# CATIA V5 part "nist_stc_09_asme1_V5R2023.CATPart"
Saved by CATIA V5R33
Part number: NIST PMI FTC 09 ASME1
Revision: D
Description: NIST PMI test model downloaded from http://go.usa.gov/mGVm
Bounding box of the stored display mesh (mm): x -95.25 to 95.25, y 0 to 9.642, z -139.7 to 139.7
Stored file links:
  C:\Users\rla3\OneDrive - NIST\STEP\NIST Test Models\STC\NIST_STC\09\V5\nist_stc_09_asme1_V5R2023-20231206.CATPart
  E:\users\dgn\TPS V5\Import-export annotations\Step\PMI representation 2015\NIST UC\nist_ftc_09_asme1_ct5240_rd - 0.CATPart
  E:\DownloadOfCXR29\win_b64\resources\graphic\CATTPSGeneralTolerance.xlsx
  C:\Program Files\Dassault Systemes\B32\win_b64\resources\graphic\CATTPSGeneralTolerance.xlsx
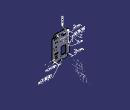
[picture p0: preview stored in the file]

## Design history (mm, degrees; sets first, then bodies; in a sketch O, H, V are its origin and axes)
TTRSSet1
f4a2d38f3ddc11d3a929006094b99c4b_11 "CATTPSSet"
Set1 "MBD_A_PMI"
  Plane1: type Equation, A -0.57735, B 0.57735, C 0.57735, Length 20, RefPoint vertex [face of Chamfer4 | end face of Pad1 | face of Pad1 from Sketch7.L15]
  Point1: type Center, Curve edge [end face of Pad1 | face of Chamfer1]
  Plane2: type OffsetPt, RefPlane face of Pad1 from Sketch7.L15, RefPoint Point1
  Intersect1: ToIntersect1 Chamfer1, ToIntersect2 Plane2
Set2 "MBD_B"
  Sketch1 on end face of Pad1, origin (0, 3.0378, 0), H (-1, 0, 0), V (0, 0, 1)
    arc A1 centre (-50.8, 12.7) radius 34.29 from (-66.509, -17.78) to (-81.28, -3.009) ccw
    point P1 (-50.8, 12.7)
    point P2 (-81.28, -3.009)
    point P3 (-66.509, -17.78)
    line L1 (-64.0699, -20.2137) -> (-63.1677, -17.9758)
    point P5 (-63.1677, -17.9758)
    line L2 (-81.28, -3.009) -> (-83.717, -0.5681)
    line L3 (-83.717, -0.5681) -> (-81.4789, 0.334)
    line L4 (-81.4789, 0.334) -> (-81.28, -3.009)
    polyline C1
    construction line L5 (-50.8, 12.7) -> (-53.3201, 12.7)
    construction line L6 (-50.8, 12.7) -> (-50.8, 10.3697)
    reference projected arc E1 centre (-50.8, 12.7) radius 4.7625 from (-52.578, 17.1182) to (-49.022, 17.1182) ccw from edge [end face of Pad1 | face of Pocket2 from Sketch15.A1]
    point P10 (-63.6219, -19.1025)
    line L7 (-66.509, -17.78) -> (-63.1677, -17.9758)
    line L8 (-66.5086, -17.7802) -> (-64.0704, -20.2149)
    point P12 (-66.5086, -17.7802)
    point P13 (-64.0704, -20.2149)
    radius A1 = 34.29
    distance L5 P3 = 30.48
    distance L6 P2 = 30.48
    length L1 = 2.413
    distance L1 P3 = 3.1722
    angle L1 L7 = 71.3955
    length L8 = 3.4456
    angle L8 L1 = 67
    length L3 = 2.413
    distance L3 P2 = 3.175
    angle L3 L2 = 67
    coincidence: L1 P1, L3 P1, P10 L1, P10 A1, L7 P5, P12 A1, P13 L1
    horizontal: L5 H
    vertical: L6 V
    concentricity: E1 P1
  Sketch2 on end face of Pad1, origin (0, 3.0378, 0), H (-1, 0, 0), V (0, 0, 1)
    reference projected circle E1 centre (57.15, 38.4) radius 3.175 from edge [end face of Pad1 | face of RectPattern2]
    reference projected circle E2 centre (0.15, -101.6) radius 3.175 from edge [end face of Pad1 | face of RectPattern2]
    axis line L1 (0.15, -101.6) -> (57.15, 38.4)
    point P1 (0.15, -101.6)
    point P2 (57.15, 38.4)
    point P3 (28.65, -31.6)
    concentricity: P1 E2, P2 E1
    midpoint: P3 L1
    coincidence: P3 L1
  AxisSystem1 "AF": origin (-28.65, 3.0378, -31.6), X (1, 0, 0), Y (0, 1, 0), Z (0, 0, 1)
  AxisSystem2 "ABC": origin (-82.55, 3.0378, 107.95), X (1, 0, 0), Y (0, 0, -1), Z (0, 1, 0)
Set3 "MBD_C"
  Sketch3 on end face of Pad1, origin (0, 3.0378, 0), H (-1, 0, 0), V (0, 0, 1)
    reference projected circle E1 centre (-50.8, -15.24) radius 1.9844 from edge [end face of Pad1 | face of Hole7]
    point P1 (-50.8, -15.24)
    line L1 (-50.8, -10.16) -> (-50.8, -20.32)
    point P2 (-50.8, -10.16)
    reference projected circle E2 centre (-78.74, 12.7) radius 1.9844 from edge [end face of Pad1 | face of CircPattern1]
    point P4 (-78.74, 12.7)
    line L2 (-83.82, 12.7) -> (-73.66, 12.7)
    point P5 (-83.82, 12.7)
    reference projected circle E3 centre (-70.5566, -7.0566) radius 1.9844 from edge [end face of Pad1 | face of CircPattern1]
    line L3 (-66.9645, -3.4645) -> (-74.1487, -10.6487)
    point P7 (-66.9645, -3.4645)
    point P8 (-74.1487, -10.6487)
    point P9 (-70.5566, -7.0566)
    point P10 (-50.8, 12.7)
    point P11 (-66.6352, -10.3194)
    arc A1 centre (-50.8, 12.7) radius 27.94 from (-73.8194, -3.1352) to (-66.6352, -10.3194) ccw
    point P12 (-73.8194, -3.1352)
    construction line L4 (-50.8, 12.7) -> (-89.9713, -15.3816)
    angle L1 L3 = 45
    radius A1 = 27.94
    length L2 = 10.16
    distance P4 P5 = 5.08
    length L3 = 10.16
    distance P9 P8 = 5.08
    length L1 = 10.16
    distance P1 P2 = 5.08
    distance L3 P12 = 5.08
    distance L3 P11 = 5.08
    concentricity: P1 E1, P4 E2, P9 E3
    vertical: L1 V
    coincidence: L1 P1, L2 P4, P9 L3, P10 L3, P10 L2
    horizontal: L2 H
  AxisSystem3 "AGH": origin (50.8, 3.0378, 12.7), X (1, 0, 0), Y (0, 0, -1), Z (0, 1, 0)
  Sketch4 on end face of Pad1, origin (0, 3.0378, 0), H (-1, 0, 0), V (0, 0, 1)
    arc A1 centre (-50.8, 12.7) radius 25.9556 from (-69.1534, -5.6534) to (-72.7556, -1.1436) cw
    point P2 (-69.1534, -5.6534)
    reference projected circle E1 centre (-70.5566, -7.0566) radius 1.9844 from edge [end face of Pad1 | face of CircPattern1]
    reference projected arc E2 centre (-50.8, 12.7) radius 27.94 from (-73.8194, -3.1352) to (-66.6352, -10.3194) ccw from Sketch3.A1
    reference projected line E3 (-66.9645, -3.4645) -> (-74.1487, -10.6487) from Sketch3.L3
    arc A2 centre (-50.8, 12.7) radius 29.9244 from (-71.9597, -8.4597) to (-76.2178, -3.0926) cw
    point P5 (-71.9597, -8.4597)
    reference projected circle E4 centre (-70.5566, -7.0566) radius 1.9844 from edge [end face of Pad1 | face of CircPattern1]
    reference projected arc E5 centre (-50.8, 12.7) radius 27.94 from (-73.8194, -3.1352) to (-66.6352, -10.3194) ccw from Sketch3.A1
    reference projected line E6 (-66.9645, -3.4645) -> (-74.1487, -10.6487) from Sketch3.L3
    tangency: A1 E1, A2 E4
    concentricity: A1 E2, A2 E5
    coincidence: P2 E3, P5 E6
  Sketch5 on end face of Pad1, origin (0, 3.0378, 0), H (-1, 0, 0), V (0, 0, 1)
    line L1 (-50.8, 12.7) -> (-77.7835, -8.4552)
    point P1 (-50.8, 12.7)
    point P3 (-74.3496, -5.763)
    reference projected arc E1 centre (-50.8, 12.7) radius 29.9244 from (-76.2178, -3.0926) to (-71.9597, -8.4597) ccw from Sketch4.A2
    reference projected point E2 (-50.8, 12.7) from vertex [YZ plane of AxisSystem3 | ZX plane of AxisSystem3 | XY plane of AxisSystem3]
    point P4 (-71.2263, -3.3144)
    reference projected arc E3 centre (-50.8, 12.7) radius 25.9556 from (-72.7556, -1.1436) to (-69.1534, -5.6534) ccw from Sketch4.A1
    coincidence: P3 L1, P3 E1, P1 E2, P4 L1, P4 E3
  Line1: type PtPt, FirstPoint Sketch3.P8, SecondPoint Sketch3.P7
  Extrude1: Element1 Line1, Lim1 2.54, Lim2 0, Direction end face of Pad1
Set4 "MBD_D"
  Sketch6 on end face of Pad1, origin (0, 3.0378, 0), H (-1, 0, 0), V (0, 0, 1)
    reference projected circle E1 centre (-66.0374, 91.44) radius 3.5687 from edge [end face of Pad1 | face of RectPattern5]
    point P1 (-66.0374, 91.44)
    line L1 (-71.1174, 91.44) -> (-60.9574, 91.44)
    point P2 (-71.1174, 91.44)
    line L2 (-66.0374, 96.52) -> (-66.0374, 86.36)
    point P4 (-66.0374, 96.52)
    length L2 = 10.16
    distance P4 L1 = 5.08
    length L1 = 10.16
    distance P2 L2 = 5.08
    concentricity: P1 E1
    horizontal: L1 H
    coincidence: P1 L1, P1 L2
    vertical: L2 V
  AxisSystem4 "ADB": origin (-31.75, 3.0378, 91.44), X (1, 0, 0), Y (0, 0, -1), Z (0, 1, 0)
  AxisSystem5 "ABC": origin (-82.55, 3.0378, 107.95), X (1, 0, 0), Y (0, 0, -1), Z (0, 1, 0)
Set5 "MBD_A"
  AxisSystem6 "ABC": origin (-82.55, 3.0378, 107.95), X (1, 0, 0), Y (0, 0, -1), Z (0, 1, 0)
Set6
  Point2: type Center, Curve edge [end face of Pad1 | face of Chamfer1]
  Point3: type Center, Curve edge [end face of Pad1 | face of Pocket2 from Sketch15.A1]
  Point4: type Center, Curve edge [end face of Pad1 | face of Hole5]
  Plane3: type Between, Element1 face of Pocket3 from Sketch17.L3, Element2 face of Pocket3 from Sketch17.L2, Ratio 0.5
  Extract1: ExtractElem face of Pocket3 from Sketch17.A2
  Extract2: ExtractElem face of Pocket3 from Sketch17.A1
  Intersect2: ToIntersect1 Plane3, ToIntersect2 Extract1
  Intersect3: ToIntersect1 Plane3, ToIntersect2 Extract2
  Point5: type OnCurve, Support Intersect2, Ratio 0.5
  Point6: type OnCurve, Support Intersect3, Ratio 0.5
  Plane4: type Tangent, Support Extract1, RefPoint Point5
  Plane5: type Tangent, Support Extract2, RefPoint Point6
  Plane6: type Between, Element1 face of RectPattern6, Element2 face of RectPattern6, Ratio 0.5
  Extract3: ExtractElem face of RectPattern6
  Extract4: ExtractElem face of RectPattern6
  Intersect4: ToIntersect1 Plane6, ToIntersect2 Extract4
  Intersect5: ToIntersect1 Plane6, ToIntersect2 Extract3
  Point7: type OnCurve, Support Intersect4, Ratio 0.5
  Point8: type OnCurve, Support Intersect5, Ratio 0.5
  Plane7: type Tangent, Support Extract4, RefPoint Point7
  Plane8: type Tangent, Support Extract3, RefPoint Point8
Body1 (main body)
  Sketch7 on zx-plane, origin (0, 0, 0), H (-1, 0, 0), V (0, 0, 1)
    line L1 (-74.6125, 139.7) -> (74.6125, 139.7)
    line L2 (95.25, 117.475) -> (95.25, -117.475)
    construction line L3 (74.6125, -139.7) -> (-74.6125, -139.7)
    line L4 (-95.25, -117.475) -> (-95.25, 117.475)
    construction line L5 (0, -160) -> (0, 150)
    axis line L6 (150, 0) -> (-110, 0)
    line L7 (-74.6125, 139.7) -> (-74.6125, 117.475)
    line L8 (-74.6125, 117.475) -> (-95.25, 117.475)
    line L9 (74.6125, 139.7) -> (74.6125, 117.475)
    line L10 (74.6125, 117.475) -> (95.25, 117.475)
    line L11 (-95.25, -117.475) -> (-74.6125, -117.475)
    line L12 (-74.6125, -117.475) -> (-74.6125, -139.7)
    line L13 (95.25, -117.475) -> (74.6125, -117.475)
    line L14 (74.6125, -117.475) -> (74.6125, -139.7)
    line L15 (-74.6125, -139.7) -> (74.6125, -139.7)
    distance L1 L3 = 279.4
    distance L4 L2 = 190.5
    distance L5 L4 = 95.25
    distance L3 L6 = 139.7
    length L4 = 234.95
    length L3 = 149.225
    distance L12 L5 = 74.6125
    distance L6 L11 = 117.475
    horizontal: L6 H, L3 H, L1 H, L8 H, L10 H, L11 H, L13 H
    coincidence: L5 V, L6 H, L10 L8, L14 L9, L11 L13, L12 L7
    vertical: L2 V, L4 V, L14 V, L9 V, L12 V, L7 V
  Pad1: profile Sketch7, direction (0, 1, 0), length 3.0378
  Sketch8 on end face of Pad1, origin (75.874, 3.0378, 103.1133), H (1, 0, 0), V (0, 0, -1)
    point P1 (6.676, -4.8367)
    reference intersected line E1 through (-75.874, 0) direction (0, 1) from yz-plane
    reference intersected line E2 through (0, 103.1133) direction (1, 0) from xy-plane
    distance P1 E1 = 82.55
    distance E2 P1 = 107.95
  Hole1: placed by Sketch8, at (82.55, 3.0378, 107.95) direction (0, -1, 0), diameter 5.9436, through (limit type 6)
  Fillet1: radius 6.35, on edge [face of Pad1 from Sketch7.L8 | face of Pad1 from Sketch7.L7]; edge [face of Pad1 from Sketch7.L9 | face of Pad1 from Sketch7.L10]; edge [face of Pad1 from Sketch7.L13 | face of Pad1 from Sketch7.L14]; edge [face of Pad1 from Sketch7.L12 | face of Pad1 from Sketch7.L11]
  Sketch9 on end face of Pad1, origin (32.8752, 3.0378, 131.8981), H (1, 0, 0), V (0, 0, -1)
    point P1 (-13.8252, 261.4381)
    reference intersected line E2 through (-32.8752, 0) direction (0, 1) from yz-plane
    reference intersected line E3 through (0, 131.8981) direction (1, 0) from xy-plane
    distance P1 E2 = 19.05
    distance E3 P1 = 129.54
  Hole2: placed by Sketch9, at (19.05, 3.0378, -129.54) direction (0, -1, 0), diameter 6.35, through (limit type 6)
  RectPattern1: of Hole2, direction 1 instances 3, spacing 19.05, along edge [face of Pad1 from Sketch7.L1 | end face of Pad1] reversed
  Sketch10 on end face of Pad1, origin (53.7045, 3.0378, 105.0288), H (1, 0, 0), V (0, 0, -1)
    point P1 (-110.8545, 206.6288)
    reference intersected line E1 through (-53.7045, 0) direction (0, 1) from yz-plane
    reference intersected line E2 through (0, 105.0288) direction (1, 0) from xy-plane
    distance P1 E1 = 57.15
    distance E2 P1 = 101.6
  Hole3: placed by Sketch10, at (-57.15, 3.0378, -101.6) direction (0, -1, 0), diameter 6.35, through (limit type 6)
  RectPattern2: of Hole3, direction 1 instances 2, spacing 57, along edge [face of Pad1 from Sketch7.L1 | end face of Pad1], direction 2 instances 2, spacing 140, along edge [face of Pad1 from Sketch7.L4 | end face of Pad1] reversed
  Sketch11 on end face of Pad1, origin (0, 3.0378, 0), H (-1, 0, 0), V (0, 0, 1)
    point P1 (5.649, -11.6078)
    line L1 (5.649, -11.6078) -> (24.3053, -11.6078)
    line L2 (55.649, -11.6078) -> (55.649, -45.2528)
    line L3 (55.649, -91.6078) -> (37.0053, -91.6078)
    line L4 (5.649, -91.6078) -> (5.649, -57.9528)
    point P2 (55.649, -11.6078)
    point P4 (5.649, -91.6078)
    arc A1 centre (55.649, -51.6028) radius 6.35 from (55.649, -57.9528) to (55.649, -45.2528) ccw
    point P5 (55.649, -51.6028)
    arc A2 centre (30.6553, -11.6078) radius 6.35 from (37.0053, -11.6078) to (24.3053, -11.6078) ccw
    point P6 (30.6553, -11.6078)
    arc A3 centre (5.649, -51.6028) radius 6.35 from (5.649, -45.2528) to (5.649, -57.9528) ccw
    point P7 (5.649, -51.6028)
    arc A4 centre (30.6553, -91.6078) radius 6.35 from (24.3053, -91.6078) to (37.0053, -91.6078) ccw
    point P8 (30.6553, -91.6078)
    construction line L5 (30.6553, 11.6851) -> (30.6553, -11.6078)
    axis line L6 (55.649, -51.6028) -> (5.649, -51.6028)
    line L7 (55.649, -57.9528) -> (55.649, -91.6078)
    line L8 (5.649, -45.2528) -> (5.649, -11.6078)
    line L9 (37.0053, -11.6078) -> (55.649, -11.6078)
    line L10 (24.3053, -91.6078) -> (5.649, -91.6078)
    reference intersected line E1 through (0, 0) direction (-1, 0) from xy-plane
    reference intersected line E2 through (0, 0) direction (0, -1) from yz-plane
    distance L6 L3 = 40.005
    distance L5 L4 = 25.0063
    radius A2 = 6.35
    radius A1 = 6.35
    radius A4 = 6.35
    radius A3 = 6.35
    distance P4 P1 = 80
    distance P1 P2 = 50
    distance L9 E1 = 11.6078
    distance L8 E2 = 5.649
    horizontal: L1 H, L3 H
    vertical: L2 V, L4 V
    coincidence: P7 L4, P6 L1, P8 L3, P5 L2, P8 L5, L2 L7, L9 L1, L3 L10, L8 L4
  Pocket1: profile Sketch11, direction (0, -1, 0), through (limit type 6)
  RectPattern3: of Hole1, direction 1 instances 2, spacing 165.1, along edge [face of Pad1 from Sketch7.L1 | end face of Pad1] reversed, direction 2 instances 2, spacing 215.9, along edge [face of Pad1 from Sketch7.L4 | end face of Pad1]
  Chamfer1: length 0.762, second length 0.762, on edge [end face of Pad1 | face of Hole1]; edge [end face of Pad1 | face of RectPattern3] (x3)
  Chamfer2: length 6.35, second length 6.35, on edge [face of Pad1 from Sketch7.L4 | face of Pad1 from Sketch7.L8]; edge [face of Pad1 from Sketch7.L10 | face of Pad1 from Sketch7.L2]; edge [face of Pad1 from Sketch7.L11 | face of Pad1 from Sketch7.L4]; edge [face of Pad1 from Sketch7.L2 | face of Pad1 from Sketch7.L13]
  Chamfer3: length 12.7, angle 30, on edge [face of Pad1 from Sketch7.L7 | face of Pad1 from Sketch7.L1]; edge [face of Pad1 from Sketch7.L1 | face of Pad1 from Sketch7.L9]
  Chamfer4: length 12.7, angle 30, on edge [face of Pad1 from Sketch7.L15 | face of Pad1 from Sketch7.L12]; edge [face of Pad1 from Sketch7.L14 | face of Pad1 from Sketch7.L15]
  Sketch12 on end face of Pad1, origin (53.7613, 3.0378, -81.0134), H (1, 0, 0), V (0, 0, -1)
    point P1 (-104.5613, -172.4534)
    reference intersected line E1 through (0, -81.0134) direction (1, 0) from xy-plane
    reference intersected line E2 through (-53.7613, 0) direction (0, 1) from yz-plane
    distance P1 E1 = 91.44
    distance E2 P1 = 50.8
  Hole4: placed by Sketch12, at (-50.8, 3.0378, 91.44) direction (0, -1, 0), diameter 5.6134, through (limit type 6)
  RectPattern4: of Hole4, direction 1 instances 2, spacing 38.1, along edge [face of Pad1 from Sketch7.L15 | end face of Pad1] reversed, direction 2 instances 2, spacing 215.9
  Sketch13 on end face of Pad1, origin (33.0099, 3.0378, -92.3254), H (1, 0, 0), V (0, 0, -1)
    point P1 (-64.7599, -183.7654)
    reference intersected line E1 through (0, -92.3254) direction (1, 0) from xy-plane
    reference intersected line E2 through (-33.0099, 0) direction (0, 1) from yz-plane
    distance P1 E1 = 91.44
    distance E2 P1 = 31.75
  Hole5: placed by Sketch13, at (-31.75, 3.0378, 91.44) direction (0, -1, 0), diameter 19.05, through (limit type 6)
  Sketch14 on end face of Pad1, origin (-47.4372, 3.0378, -73.8358), H (1, 0, 0), V (0, 0, -1)
    point P1 (75.3745, -165.2758)
    reference intersected line E1 through (0, -73.8358) direction (1, 0) from xy-plane
    reference intersected line E2 through (47.4372, 0) direction (0, 1) from yz-plane
    distance E1 P1 = 91.44
    distance E2 P1 = 27.9374
  Hole6: placed by Sketch14, at (27.9374, 3.0378, 91.44) direction (0, -1, 0), diameter 7.1374, through (limit type 6)
  RectPattern5: of Hole6, direction 1 instances 3, spacing 19.05, along edge [face of Pad1 from Sketch7.L15 | end face of Pad1] reversed, direction 2 instances 2, spacing 215.9
  Sketch15 on end face of Pad1, origin (0, 3.0378, 0), H (-1, 0, 0), V (0, 0, 1)
    arc A1 centre (-50.8, 12.7) radius 4.7625 from (-52.578, 17.1182) to (-49.022, 17.1182) ccw
    point P1 (-50.8, 12.7)
    axis line L1 (-50.8, 12.7) -> (-50.8, 29.6508)
    line L2 (-52.578, 20.32) -> (-52.578, 17.1182)
    line L3 (-49.022, 20.32) -> (-49.022, 17.1182)
    arc A2 centre (-50.8, 20.32) radius 1.778 from (-49.022, 20.32) to (-52.578, 20.32) ccw
    point P3 (-50.8, 20.32)
    point P4 (-49.022, 20.32)
    reference intersected line E1 through (0, 0) direction (-1, 0) from xy-plane
    reference intersected line E2 through (0, 0) direction (0, -1) from yz-plane
    radius A1 = 4.7625
    distance L3 L2 = 3.556
    distance P1 P3 = 7.62
    distance E1 P1 = 12.7
    distance E2 L1 = 50.8
    vertical: L1 V, L2 V, L3 V
    coincidence: P3 L1, A2 P4, P4 L3
    tangency: A2 L3, A2 L2
  Pocket2: profile Sketch15, direction (0, -1, 0), through (limit type 6)
  Sketch16 on end face of Pad1, origin (-52.5866, 3.0378, 15.7994), H (1, 0, 0), V (0, 0, -1)
    point P1 (103.3866, 31.0394)
    reference intersected line E1 through (0, 15.7994) direction (1, 0) from xy-plane
    reference intersected line E2 through (52.5866, 0) direction (0, 1) from yz-plane
    distance P1 E1 = 15.24
    distance E2 P1 = 50.8
  Hole7: placed by Sketch16, at (50.8, 3.0378, -15.24) direction (0, -1, 0), diameter 3.9688, through (limit type 6)
  CircPattern1: of Hole7, instances 3, angular step 45, axis from face of Pocket2 from Sketch15.A1
  Sketch17 on end face of Pad1, origin (0, 3.0378, 0), H (-1, 0, 0), V (0, 0, 1)
    construction line L1 (-57.15, -95.25) -> (-38.1, -95.25)
    line L2 (-57.15, -92.075) -> (-38.1, -92.075)
    line L3 (-38.1, -98.425) -> (-57.15, -98.425)
    arc A1 centre (-38.1, -95.25) radius 3.175 from (-38.1, -92.075) to (-38.1, -98.425) cw
    arc A2 centre (-57.15, -95.25) radius 3.175 from (-57.15, -98.425) to (-57.15, -92.075) cw
    axis line L4 (-47.625, -92.075) -> (-47.625, -98.425)
    point P7 (-47.625, -92.075)
    point P8 (-47.625, -98.425)
    reference intersected line E1 through (0, 0) direction (-1, 0) from xy-plane
    reference intersected line E2 through (0, 0) direction (0, -1) from yz-plane
    distance L1 L2 = 3.175
    distance A2 A1 = 25.4
    distance E1 L1 = 95.25
    distance L4 E2 = 47.625
    horizontal: L1 H
    tangency: A1 L2, A2 L2, A1 L3, A2 L3
    vertical: L4 V
    midpoint: P7 L2, L3 P8
  Pocket3: profile Sketch17, direction (0, -1, 0), through (limit type 6)
  RectPattern6: of Pocket3, direction 1 instances 2, spacing 19.05, along edge [face of Pad1 from Sketch7.L2 | end face of Pad1], direction 2 instances 2, spacing 215.9
  Sketch18 on end face of Pad1, origin (0, 3.0378, 0), H (-1, 0, 0), V (0, 0, 1)
    construction line L1 (-61.9125, -50.8) -> (-33.3375, -50.8)
    line L2 (-61.9125, -46.0375) -> (-33.3375, -46.0375)
    line L3 (-33.3375, -55.5625) -> (-61.9125, -55.5625)
    arc A1 centre (-33.3375, -50.8) radius 4.7625 from (-33.3375, -46.0375) to (-33.3375, -55.5625) cw
    arc A2 centre (-61.9125, -50.8) radius 4.7625 from (-61.9125, -55.5625) to (-61.9125, -46.0375) cw
    axis line L4 (-47.625, -46.0375) -> (-47.625, -55.5625)
    point P7 (-47.625, -46.0375)
    point P8 (-47.625, -55.5625)
    reference intersected line E1 through (0, 0) direction (-1, 0) from xy-plane
    reference intersected line E2 through (0, 0) direction (0, -1) from yz-plane
    distance L1 L2 = 4.7625
    distance A2 A1 = 38.1
    distance L1 E1 = 50.8
    distance L4 E2 = 47.625
    horizontal: L1 H
    tangency: A1 L2, A2 L2, A1 L3, A2 L3
    coincidence: P7 L2, P8 L3
    vertical: L4 V
    midpoint: P8 L3, P7 L2
  Pocket4: profile Sketch18, direction (0, -1, 0), through (limit type 6)
  Sketch19 on end face of Pad1, origin (83.475, 3.0378, 19.7164), H (1, 0, 0), V (0, 0, -1)
    point P1 (-168.565, 38.7664)
    reference intersected line E1 through (0, 19.7164) direction (1, 0) from xy-plane
    reference intersected line E2 through (-83.475, 0) direction (0, 1) from yz-plane
    distance E1 P1 = 19.05
    distance E2 P1 = 85.09
  Hole8: placed by Sketch19, at (-85.09, 3.0378, -19.05) direction (0, -1, 0), diameter 6.35, through (limit type 6)
  RectPattern7: of Hole8, direction 1 instances 3, spacing 19.05, along edge [face of Pad1 from Sketch7.L4 | end face of Pad1] reversed, direction 2 instances 2, spacing 215.9
  Sketch20 on end face of Pad1, origin (46.5928, 3.0378, -111.2191), H (1, 0, 0), V (0, 0, -1)
    point P1 (-102.4728, -221.7091)
    reference intersected line E1 through (-46.5928, 0) direction (0, 1) from yz-plane
    reference intersected line E2 through (0, -111.2191) direction (1, 0) from xy-plane
    distance P1 E1 = 55.88
    distance P1 E2 = 110.49
  Hole9: placed by Sketch20, at (-55.88, 3.0378, 110.49) direction (0, -1, 0), diameter 3.9688, through (limit type 6)
  RectPattern8: of Hole9, direction 1 instances 2, spacing 10.16, along edge [face of Pad1 from Sketch7.L15 | end face of Pad1] reversed, direction 2 instances 2, spacing 215.9
  RectPattern9: of RectPattern8, direction 1 instances 2, spacing 38.1, along edge [face of Pad1 from Sketch7.L15 | end face of Pad1] reversed, direction 2 instances 2, spacing 215.9
  Sketch21 on end face of Pad1, origin (-44.0436, 3.0378, -67.034), H (1, 0, 0), V (0, 0, -1)
    point P1 (82.1436, -124.184)
    reference intersected line E1 through (44.0436, 0) direction (0, 1) from yz-plane
    reference intersected line E2 through (0, -67.034) direction (1, 0) from xy-plane
    distance E1 P1 = 38.1
    distance E2 P1 = 57.15
  Hole10: placed by Sketch21, at (38.1, 3.0378, 57.15) direction (0, -1, 0), diameter 8.001, through (limit type 6)
  RectPattern10: of Hole10, direction 1 instances 2, spacing 19.05, along edge [face of Pad1 from Sketch7.L15 | end face of Pad1] reversed, direction 2 instances 2, spacing 215.9
  Fillet2: radius 3.175, on edge [face of Pocket1 from Sketch11.L10 | face of Pocket1 from Sketch11.L4]; edge [face of Pocket1 from Sketch11.L8 | face of Pocket1 from Sketch11.L1]; edge [face of Pocket1 from Sketch11.L9 | face of Pocket1 from Sketch11.L2]; edge [face of Pocket1 from Sketch11.L7 | face of Pocket1 from Sketch11.L3]
  Sketch22 on end face of Pad1, origin (0, 3.0378, 0), H (-1, 0, 0), V (0, 0, 1)
    point P1 (-12.7, 118.11)
    reference intersected line E1 through (0, 0) direction (0, -1) from yz-plane
    reference intersected line E2 (-74.6125, 139.7) -> (74.6125, 139.7) from face of Pad1 from Sketch7.L1
    point P2 (-12.7, 118.11)
    point P3 (-12.7, 118.11)
    point P4 (-26.2068, 116.7906)
    point P5 (-32.4699, 114.5929)
    point P6 (-37.6134, 113.9143)
    point P7 (-38.7059, 115.0068)
    point P8 (-15.8025, 118.11)
    point P9 (-15.8025, 106.8665)
    point P10 (-15.8025, 118.11)
    point P11 (-16.7397, 106.501)
    point P12 (-15.8025, 106.8665)
    point P13 (-26.2068, 116.7906)
    point P14 (-16.7397, 106.501)
    point P15 (-32.4699, 103.11)
    point P16 (-32.4699, 114.5929)
    point P17 (-29.3377, 103.11)
    point P18 (-32.4699, 103.11)
    point P19 (-29.3377, 114.5181)
    point P20 (-29.3377, 103.11)
    point P21 (-28.62, 114.8343)
    point P22 (-29.3377, 114.5181)
    point P23 (-18.3552, 103.7339)
    point P24 (-28.62, 114.8343)
    point P25 (-18.3552, 103.7339)
    point P26 (-12.7, 105.9479)
    point P27 (-12.7, 105.9479)
    point P28 (-37.6134, 103.11)
    point P29 (-34.4811, 103.11)
    point P30 (-37.6134, 113.9143)
    point P31 (-37.6134, 103.11)
    point P32 (-53.4174, 115.0068)
    point P33 (-38.7059, 115.0068)
    point P34 (-53.4174, 115.0068)
    point P35 (-53.3599, 112.1904)
    point P36 (-44.3081, 112.1904)
    point P37 (-53.3599, 112.1904)
    point P38 (-43.9641, 103.11)
    point P39 (-44.3081, 112.1904)
    point P40 (-69.5674, 103.11)
    point P41 (-43.9641, 103.11)
    point P42 (-69.5674, 106.271)
    point P43 (-69.5674, 103.11)
    point P44 (-63.1581, 106.271)
    point P45 (-69.5674, 106.271)
    point P46 (-63.1581, 118.11)
    point P47 (-63.1581, 106.271)
    point P48 (-60.0556, 118.11)
    point P49 (-63.1581, 118.11)
    point P50 (-60.0556, 106.271)
    point P51 (-60.0556, 118.11)
    point P52 (-44.3655, 106.271)
    point P53 (-60.0556, 106.271)
    point P54 (-44.3655, 106.271)
    point P55 (-44.2506, 109.0871)
    point P56 (-53.8773, 109.0871)
    point P57 (-44.2506, 109.0871)
    point P58 (-53.8773, 118.11)
    point P59 (-53.8773, 109.0871)
    point P60 (-38.6768, 118.11)
    point P61 (-53.8773, 118.11)
    point P62 (-34.4811, 113.9143)
    point P63 (-38.6768, 118.11)
    point P64 (-34.4811, 103.11)
    point P65 (-34.4811, 113.9143)
    point P66 (-12.7, 118.11)
    point P67 (-12.7, 118.11)
    line L1 (-34.4811, 103.11) -> (-34.4811, 113.9143)
    arc A1 centre (-38.6768, 113.9143) radius 4.1957 from (-34.4811, 113.9143) to (-38.6768, 118.11) ccw
    line L2 (-38.6768, 118.11) -> (-53.8773, 118.11)
    arc A2 centre (-53.1589, 113.5985) radius 4.5683 from (-53.8773, 118.11) to (-53.8773, 109.0871) ccw
    line L3 (-53.8773, 109.0871) -> (-44.2506, 109.0871)
    arc A3 centre (-44.2506, 107.6767) radius 1.4104 from (-44.3655, 106.271) to (-44.2506, 109.0871) ccw
    line L4 (-44.3655, 106.271) -> (-60.0556, 106.271)
    line L5 (-60.0556, 106.271) -> (-60.0556, 118.11)
    line L6 (-60.0556, 118.11) -> (-63.1581, 118.11)
    line L7 (-63.1581, 118.11) -> (-63.1581, 106.271)
    line L8 (-63.1581, 106.271) -> (-69.5674, 106.271)
    line L9 (-69.5674, 106.271) -> (-69.5674, 103.11)
    line L10 (-69.5674, 103.11) -> (-43.9641, 103.11)
    arc A4 centre (-43.9641, 107.6567) radius 4.5467 from (-43.9641, 103.11) to (-44.3081, 112.1904) ccw
    line L11 (-44.3081, 112.1904) -> (-53.3599, 112.1904)
    arc A5 centre (-53.2372, 113.6017) radius 1.4166 from (-53.4174, 115.0068) to (-53.3599, 112.1904) ccw
    line L12 (-53.4174, 115.0068) -> (-38.7059, 115.0068)
    line L13 (-37.6134, 113.9143) -> (-37.6134, 103.11)
    line L14 (-37.6134, 103.11) -> (-34.4811, 103.11)
    line L15 (-12.7, 118.11) -> (-12.7, 105.9479)
    arc A6 centre (-15.961, 105.9479) radius 3.261 from (-18.3552, 103.7339) to (-12.7, 105.9479) ccw
    line L16 (-18.3552, 103.7339) -> (-28.62, 114.8343)
    arc A7 centre (-28.9245, 114.5528) radius 0.4146 from (-28.62, 114.8343) to (-29.3377, 114.5181) ccw
    line L17 (-29.3377, 114.5181) -> (-29.3377, 103.11)
    line L18 (-29.3377, 103.11) -> (-32.4699, 103.11)
    line L19 (-32.4699, 103.11) -> (-32.4699, 114.5929)
    line L20 (-26.2068, 116.7906) -> (-16.7397, 106.501)
    arc A8 centre (-16.3424, 106.8665) radius 0.5399 from (-16.7397, 106.501) to (-15.8025, 106.8665) ccw
    line L21 (-15.8025, 106.8665) -> (-15.8025, 118.11)
    line L22 (-15.8025, 118.11) -> (-12.7, 118.11)
    arc A9 centre (-38.7059, 113.9143) radius 1.0926 from (-37.6134, 113.9143) to (-38.7059, 115.0068) ccw
    arc A10 centre (-28.9528, 114.5929) radius 3.5171 from (-26.2068, 116.7906) to (-32.4699, 114.5929) ccw
    distance P1 E1 = 12.7
    distance E2 P1 = 21.59
    fix: P4, P5, P6, P7, P8, P9, P10, P11, P12, P13, P14, P15, P16, P17, P18, P19, P20, P21, P22, P23, P24, P25, P26, P27, P28, P29, P30, P31, P32, P33, P34, P35, P36, P37, P38, P39, P40, P41, P42, P43, P44, P45, P46, P47, P48, P49, P50, P51, P52, P53, P54, P55, P56, P57, P58, P59, P60, P61, P62, P63, P64, P65, L1, A1, L2, A2, L3, A3, L4, L5, L6, L7, L8, L9, L10, A4, L11, A5, L12, L13, L14, A6, L16, A7, L17, L18, L19, L20, A8, L21, A9, A10, L22, L15, P2
    coincidence: P66 P67
  Pocket5: profile Sketch22, direction (0, -1, 0), length 1.27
